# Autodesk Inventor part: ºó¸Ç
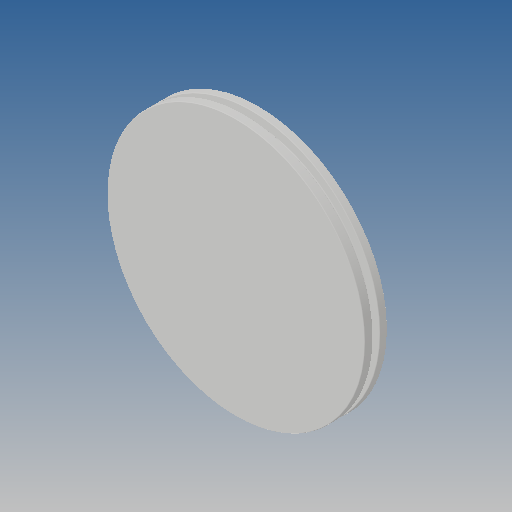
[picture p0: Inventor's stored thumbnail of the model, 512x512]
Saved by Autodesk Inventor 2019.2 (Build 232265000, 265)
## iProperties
Created: 2013-07
Part Number: ºó¸Ç
Material: Ogólny
Document SubType Name: Modeling
Designer: CADENGINEERING4
Density: 1 g/cm^3
Appearance: Domyślna
Author: CADENGINEERING4
Revision Number: ÈÎºÎ
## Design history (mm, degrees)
feature "CALC100-ºó¸Ç.bak-1-solid1"
node "Bryła1"
